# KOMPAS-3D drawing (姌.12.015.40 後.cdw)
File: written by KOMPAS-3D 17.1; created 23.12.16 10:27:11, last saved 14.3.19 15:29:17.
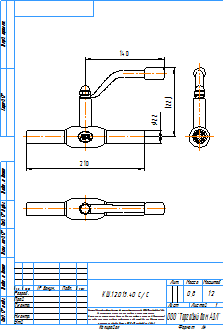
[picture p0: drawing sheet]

Sheet 1: A4, portrait

Title block, sheet 1: name: КШ.12.015.40 С/С; material: Сталь 20  ГОСТ 1050-88; mass: 0,8; sheets: 1; sheet format: A4; stored path: \\adlc.lan\data\АДЛ_ПКД\3D-модели\ADL production\Шаровые краны БИВАЛ\КШ_Бивал_серия_11_12\KOMPAS_2D\КШ.12.015.40 сс.cdw

Views: Вид 1, Проекционный вид 2, Проекционный вид 3
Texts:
  Klimkovich
  ADL
  Рама для чертежей
  Лит-Масса-Масштаб
  Материал-Предприятие
  Масштаб
  Изм.
  Лист
  № докум.
  Подп.
  Дата
  Лит.
  Разраб.
  Пров.
  Т.контр.
  Листов
  Внимание! Данный продукт является объектом авторского права ООО «Торговый Дом АДЛ».
  Запрещается изменение, копирование, распространение
  (в том числе путем копирования на другие сайты и ресурсы в Интернете)
  или любое иное использование информации и объектов без предварительного
  согласия правообладателя (ООО «Торговый Дом АДЛ»).
  Н.контр.
  Утв.
  ООО "Торговый дом АДЛ"
  Изменение
  Номер документа
  Подпись
  Обозначение документа
  Наименование изделия
  Масса изделия по ГОСТ 2.109-73
  Порядковый номер листа
  Общее количество листов в документе
  Характер работы, выполненной лицом, подписавшим документ
  Наименование или индекс предприятия, выпускающего документ
  Инв. № подл.
  Подп. и дата
  Взам. инв. №
  Инв. № дубл.
  Инвентарный номер подлинника по ГОСТ 2.501-68
  Подпись принявшего подлинник в отдел технической документации
  Инвентарный номер подлинника, взамен которого выпущен данный подлинник
  Инвентарный номер дубликата по ГОСТ 2.502-68
  Подпись принявшего дубликат в отдел технической документации
  Справ. №
  Перв. примен.
  Обозначение документа, взамен или на основании которого выпущен данный документ
  Обозначение документа, в котором впервые записан данный документ
  Подпись лица, копировавшего чертеж
  Обозначение формата листа
  !Рама для чертежа
Dimensions and other numbers on the sheet: 210; 22; 122,1; 140; 1:2; 1; 0,8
